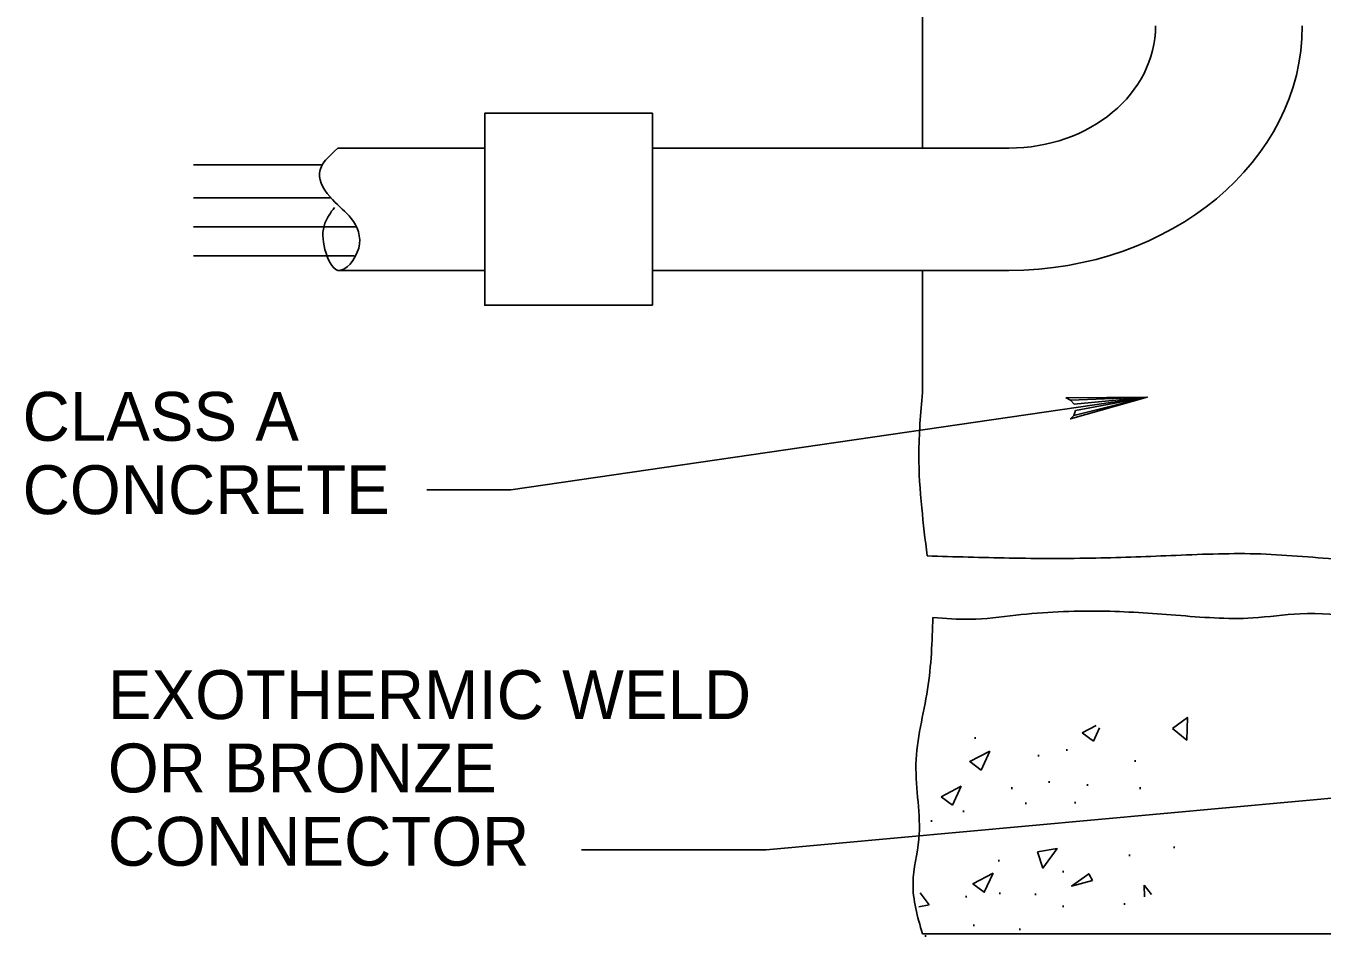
# Model space of a CAD drawing. Extents: x 638448 to 639352, y 297825 to 299013.
# Drawn here: x 639016.6 to 639105.6, y 298167.4 to 298230 of the extents above; entities that cross this region are included whole.
import ezdxf

# ---------------------------------------------------------------- set-up
doc = ezdxf.new("R2010")
doc.units = 0
doc.layers.add('2', color=7, linetype='Continuous')
doc.layers.add('3', color=7, linetype='Continuous')

msp = doc.modelspace()

# ---------------------------------------------------------------- linework, layer by layer
at = {"layer": '2'}
for p, q in [((639078.173, 298256.245), (639078.173, 298221.591)), ((639048.105, 298221.591), (639038.025, 298221.591)), ((639084.105, 298221.591), (639059.625, 298221.591)), ((639036.937, 298220.452), (639028.111, 298220.452)), ((639037.561, 298218.172), (639028.111, 298218.172)), ((639039.306, 298216.178), (639028.111, 298216.178)), ((639039.152, 298214.183), (639028.111, 298214.183)), ((639048.105, 298213.191), (639038.025, 298213.191)), ((639084.105, 298213.191), (639059.625, 298213.191)), ((639078.173, 298213.191), (639078.173, 298204.791)), ((639078.173, 298167.591), (639112.545, 298167.591))]:
    msp.add_line(p, q, dxfattribs=at)
for points in [[(639059.625, 298210.791), (639059.625, 298223.991), (639048.105, 298223.991), (639048.105, 298210.791)], [(639095.339, 298181.712), (639096.375, 298182.46), (639096.33, 298180.906)], [(639082.807, 298180.148), (639081.425, 298179.428), (639082.207, 298178.842)], [(639086.076, 298173.223), (639087.423, 298173.445), (639086.455, 298172.111)], [(639083.023, 298171.755), (639081.641, 298171.035), (639082.425, 298170.449)], [(639089.844, 298171.265), (639089.601, 298171.725), (639088.416, 298170.871)]]:
    msp.add_lwpolyline(points, close=True, dxfattribs=at)
for points in [[(639044.143, 298198.111), (639049.903, 298198.111), (639093.614, 298204.483)], [(639088.349, 298204.271), (639088.605, 298203.987), (639093.614, 298204.483), (639088.349, 298204.271), (639088.044, 298204.421), (639093.614, 298204.483), (639088.699, 298203.555), (639088.584, 298203.221), (639093.614, 298204.483), (639088.346, 298202.975), (639088.584, 298203.221)], [(639090.103, 298181.913), (639089.141, 298181.411)], [(639089.141, 298181.411), (639089.925, 298180.827)], [(639089.925, 298180.827), (639090.343, 298181.739)], [(639054.765, 298173.375), (639067.442, 298173.375), (639112.545, 298177.499)], [(639080.834, 298177.735), (639079.452, 298177.015)], [(639080.237, 298176.429), (639080.834, 298177.735)], [(639079.452, 298177.015), (639080.237, 298176.429)], [(639078.019, 298170.401), (639078.645, 298169.595)], [(639093.434, 298170.123), (639093.415, 298170.929)], [(639093.415, 298170.929), (639093.912, 298170.291)], [(639078.645, 298169.595), (639077.916, 298169.455)]]:
    msp.add_lwpolyline(points, dxfattribs=at)
for major_axis in [(10.08, 0), (20.16, 0)]:
    msp.add_ellipse((639084.106, 298229.991), major_axis=major_axis, ratio=0.833333, start_param=4.712389, end_param=6.283185, dxfattribs=at)
for points in [[(639038.025, 298221.591), (639036.751, 298219.875), (639037.651, 298218.051), (639038.94, 298216.765), (639039.453, 298214.725), (639038.025, 298213.191), (639037.137, 298214.619), (639037.137, 298216.443), (639037.781, 298217.515)], [(639078.173, 298204.791), (639077.928, 298200.519), (639078.127, 298196.863), (639078.494, 298193.563)], [(639078.494, 298193.563), (639084.141, 298193.417), (639090.089, 298193.417), (639095.585, 298193.603), (639101.419, 298193.697), (639107.141, 298193.323), (639113.985, 298193.511), (639118.473, 298193.885), (639125.205, 298193.043), (639128.234, 298193.791), (639135.189, 298193.323), (639139.341, 298193.697), (639143.829, 298193.417), (639147.643, 298193.885), (639152.078, 298193.561)], [(639152.244, 298189.381), (639148.653, 298189.209), (639140.016, 298189.771), (639130.591, 298189.583), (639119.594, 298189.863), (639112.303, 298189.117), (639104.112, 298189.583), (639100.86, 298189.303), (639095.585, 298189.489), (639090.425, 298189.771), (639084.59, 298189.489), (639081.449, 298189.209), (639078.897, 298189.343)], [(639078.897, 298189.343), (639078.525, 298184.395), (639077.729, 298179.241), (639077.928, 298174.087), (639077.527, 298171.095), (639078.173, 298167.591)]]:
    msp.add_spline(points, degree=3, dxfattribs=at)

# ---------------------------------------------------------------- texts
for p in [(639081.619, 298180.979), (639087.919, 298180.163), (639085.973, 298179.771), (639092.609, 298179.395), (639084.153, 298177.533), (639086.721, 298177.965), (639089.337, 298177.755), (639092.954, 298177.533), (639085.109, 298176.489), (639088.501, 298176.533), (639080.834, 298175.949), (639078.627, 298175.286), (639092.239, 298172.907), (639095.291, 298173.467), (639083.253, 298172.561), (639087.667, 298171.793), (639081.019, 298170.075), (639083.335, 298170.295), (639085.778, 298170.237), (639087.667, 298169.411), (639091.893, 298169.575), (639081.537, 298168.115), (639084.705, 298167.837), (639078.221, 298167.367)]:
    msp.add_text('.', height=0.893, dxfattribs=at).set_placement(p)
at = {"layer": '3'}
for s, height, p in [('CLASS A', 3.36, (639016.367, 298201.475)), ('CONCRETE', 3.36, (639016.367, 298196.435)), ('EXOTHERMIC WELD', 3.35999, (639022.22, 298182.351)), ('OR BRONZE', 3.36, (639022.22, 298177.311)), ('CONNECTOR', 3.36, (639022.22, 298172.271))]:
    msp.add_text(s, height=height, dxfattribs=at).set_placement(p)

doc.saveas('drawing.dxf')
